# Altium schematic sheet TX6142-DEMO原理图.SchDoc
size A
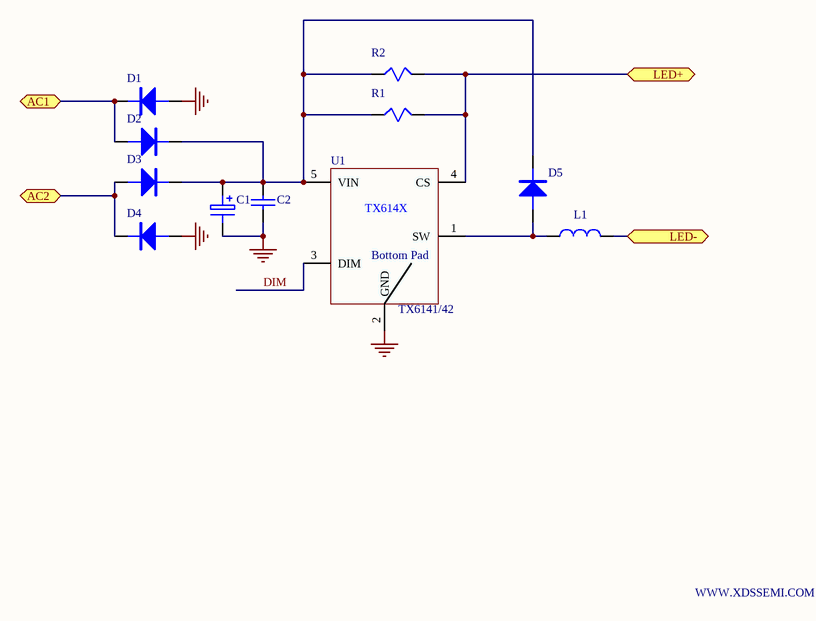
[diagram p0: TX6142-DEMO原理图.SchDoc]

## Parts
C1  (no value)  [C8*12]
C2  (no value)  [R1206]
D1  (no value)  [SMA]
D2  (no value)  [SMA]
D3  (no value)  [SMA]
D4  (no value)  [SMA]
D5  (no value)  [SMA]
L1  (no value)  [WHC1040]
R1  (no value)  [R1206]
R2  (no value)  [R1206]
U1  TX6141/42  [SOT89-5]

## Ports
AC1, AC2, LED+, LED-

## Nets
GND: C1.2 C2.2 D1.1(A) D4.1(A) U1.2(GND)
AC1: D1.2(K) D2.1(A) ; port AC1
AC2: D3.1(A) D4.2(K) ; port AC2
DIM: U1.3(DIM)
LED+: R1.2 R2.2 U1.4(CS) ; port LED+
LED-: L1.2 ; port LED-
NetC1_1: C1.1 C2.1 D2.2(K) D3.2(K) D5.2(K) R1.1 R2.1 U1.5(VIN)
NetD5_1: D5.1(A) L1.1 U1.1(SW)

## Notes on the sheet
- WWW.XDSSEMI.COM

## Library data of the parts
C1 = ELECTRO1: Electrolytic Capacitor
C2 = CAP: Capacitor
D1-D5 = DIODE
L1 = INDUCTOR
R1 R2 = RES1
U1 = TX614X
